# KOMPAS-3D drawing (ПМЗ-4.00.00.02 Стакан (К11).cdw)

Referenced files in D:\чертежи 02-04-2014\чертежи электропривод\чертежи электропривод\Изм\Правка\: Стакан.cdw
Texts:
  ПМЗ-4.00.00.02
  Стакан
  133 1 134 1 135 1 136 0 50 1|SPDS|133 1 134 1 135 1 136 0 50 1
  125 1 126 1 127 1 128 0 50 1|SPDS|125 1 126 1 127 1 128 0 50 1
  129 1 130 1 131 1 132 0 50 1|SPDS|129 1 130 1 131 1 132 0 50 1
  Ra 1,25
  js13
  Согласовано:
  ООО "Электропривод"
  max
  недорез резьбы
  *Размер для справок.
  H12, h12,  IT12/2.
  Rz 25
  БрАМЦ9-2 ГОСТ 18175-78
  ПМЗ-4.00.00.02-
  Бердников
  Лит-Масса-Масштаб
  Материал-Предприятие
  Масштаб
  Изм.
  Лист
  № докум.
  Подп.
  Дата
  Лит.
  Разраб.
  Зверев
  Пров.
  Ложкин
  Т.контр.
  Листов
  Нач. отд.
  Волосков
  Н.контр.
  Утв.
  Иванов
  ЗАО
  "МЕТТЕМ-Производство"
  Изменение
  Номер документа
  Подпись
  Обозначение документа
  Наименование изделия
  Масса изделия по ГОСТ 2.109-73
  Порядковый номер листа
  Общее количество листов в документе
  Характер работы, выполненной лицом, подписавшим документ
  Наименование или индекс предприятия, выпускающего документ
  Инв. № подл.
  Подп. и дата
  Взам. инв. №
  Инв. № дубл.
  Инвентарный номер подлинника по ГОСТ 2.501-68
  Подпись принявшего подлинник в отдел технической документации
  Инвентарный номер подлинника, взамен которого выпущен данный подлинник
  Инвентарный номер дубликата по ГОСТ 2.502-68
  Подпись принявшего дубликат в отдел технической документации
  Справ. №
  Перв. примен.
  Обозначение документа, взамен или на основании которого выпущен данный документ
  Обозначение документа, в котором впервые записан данный документ
  Подпись лица, копировавшего чертеж
  Обозначение формата листа
Dimensions and other numbers on the sheet: 70; 6; 50,9; 0,1; 0,5; 47; 35; 33,5; 46,5; 4; 53,5; 12,5*; 1; 30; 40; 32,5; 22; 4 отв.; 2,3; 20,5; 0,7; 0,3; 25; 2; 0,4; 1,5; 3; 2:1; 0,24; 07.08.14; 8.08.14; 18.09.14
